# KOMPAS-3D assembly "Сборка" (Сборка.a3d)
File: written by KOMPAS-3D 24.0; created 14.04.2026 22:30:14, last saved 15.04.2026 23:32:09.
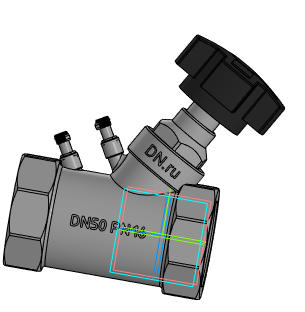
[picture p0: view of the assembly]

Document properties: Автор: tyuri; Полное имя файла: D:\Аутсорс\VB0000P-T Клапан балансировочный статический DN.ru\DN50\Исходные данные\Сборка.a3d

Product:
- Component [detail]: Деталь1  | qty 1  | Автор: tyuri; additional columns: Типовые; source file: Деталь1 - Деталь1.m3d
- Body: Тело 1  | qty 1
    Масса: 2.226476
- Component [detail]: Ручка  | designation Деталь2  | qty 1  | Масса: 0.541971; Автор: tyuri; additional columns: Типовые; source file: Деталь2 - Деталь2.m3d
- Part/product: Сборка
    Масса: 2.768447

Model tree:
1. Эскиз:2
2. Элемент вращения:1  (labels: Грань.Твердое тело1)
     Угол 1 = 360
3. Смещенная плоскость:1
     Расстояние = 40
4. Эскиз:3
5. Элемент выдавливания:1  (with: Грань.Элемент вращения:1)
     Расстояние 1 = -17.3791; Смещение 1 = 0.01
6. Эскиз:4
7. Элемент выдавливания:2  (with: Грань.Элемент вращения:1)  (labels: Грань.Твердое тело1; Твердое тело1)
     Расстояние 1 = -10.0202; Смещение 1 = 0.001; Расстояние = -35

Referenced files in D:\Аутсорс\VB0000P-T Клапан балансировочный статический DN.ru\DN50\Исходные данные\: Деталь1 - Деталь1.m3d, Деталь2 - Деталь2.m3d
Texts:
  DN50 PN16
  GOST 26.020 Pr3
  Деталь1 Деталь1
  Деталь2 Ручка
  Ось X.Начало координат
  Ось Z.Начало координат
